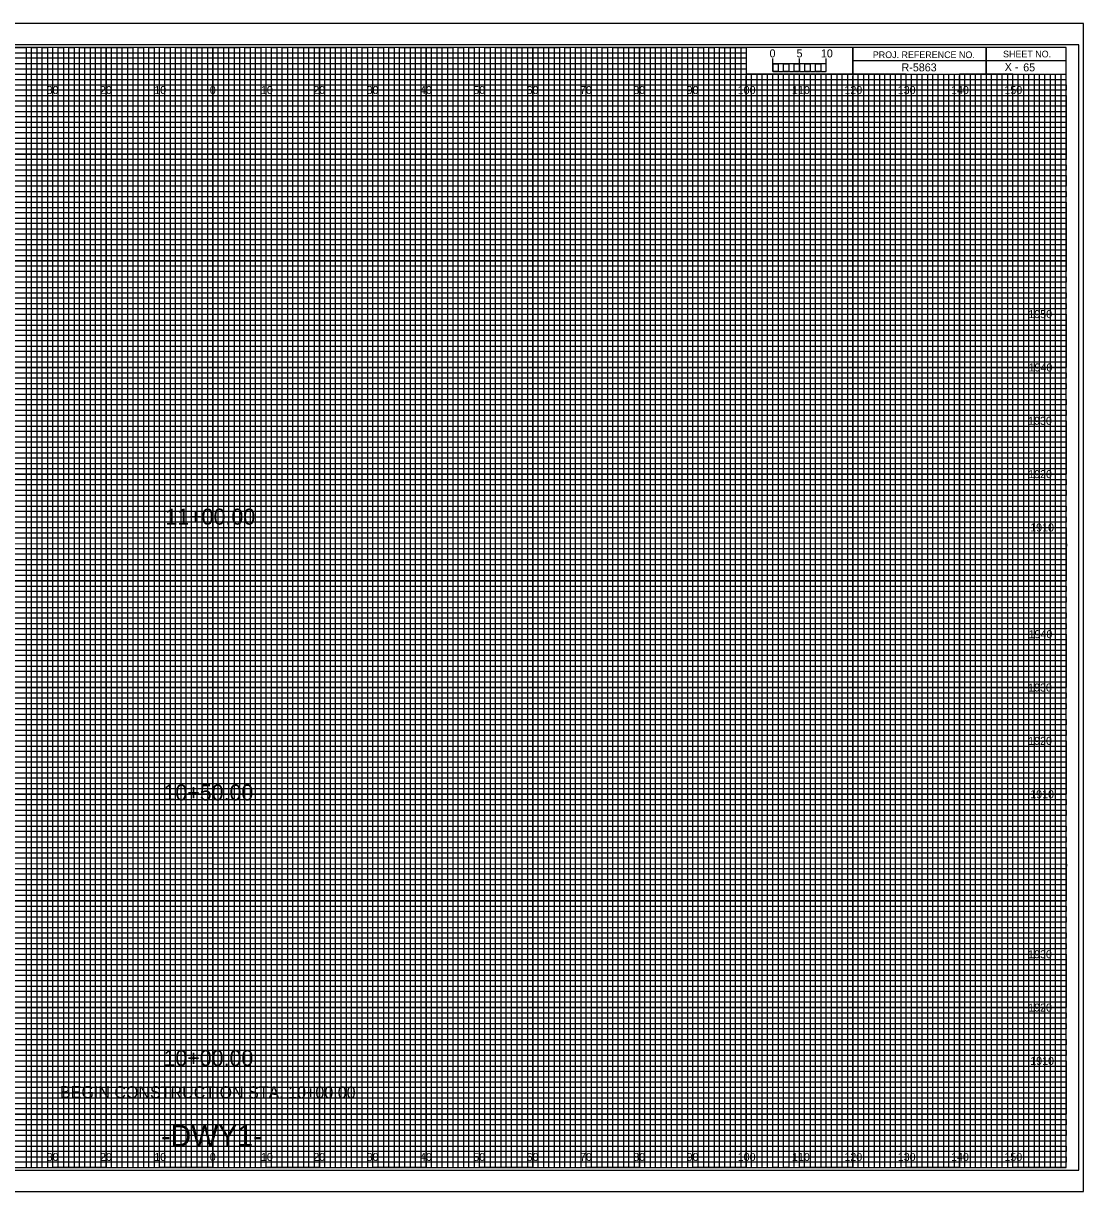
# Model space of a CAD drawing. Extents: x -13 to 323, y -4 to 214.
# Drawn here: x 124.5 to 323.3, y -4.5 to 214.5 of the extents above; entities that cross this region are included whole.
import ezdxf

# ---------------------------------------------------------------- set-up
doc = ezdxf.new("R2010")
doc.units = 0
for name, color, linetype in [('Prop XS Alignment Label', 7, 'Continuous'), ('Prop XS Bar Scale Labels', 7, 'Continuous'), ('Prop XS Elevation Labels', 7, 'Continuous'), ('Prop XS Offset Labels', 7, 'Continuous'), ('Prop XS Project Number', 7, 'Continuous'), ('Prop XS SE Text', 7, 'Continuous'), ('Prop XS Sheet Number', 7, 'Continuous'), ('Prop XS Station Labels', 7, 'Continuous'), ('Sheet Cross Section CELL', 7, 'Continuous'), ('Sheet Cross Section Grid Major CELL', 7, 'Continuous'), ('Sheet Cross Section Grid Middle CELL', 7, 'Continuous'), ('Sheet Cross Section Grid Minor 1 CELL', 7, 'Continuous'), ('Sheet Cross Section Grid Minor 2 CELL', 7, 'Continuous'), ('Sheet Cross Section Scale CELL', 7, 'Continuous'), ('Sheet Cutting Line CELL', 7, 'Continuous'), ('Sheet DOT Grid CELL', 7, 'Continuous'), ('Sheet Plot Border Inside CELL', 7, 'Continuous'), ('Sheet Plot Border Outside CELL', 7, 'Continuous')]:
    doc.layers.add(name, color=color, linetype=linetype)

msp = doc.modelspace()

# ---------------------------------------------------------------- linework, layer by layer
at = {"layer": 'Sheet Cross Section CELL'}
for p, q in [((305, 210), (305, 205)), ((305, 205), (305, 210)), ((280, 207.5), (280, 205)), ((320, 207.49), (280, 207.49)), ((280, 205), (320, 205))]:
    msp.add_line(p, q, dxfattribs=at)
for points in [[(320, 210), (0, 210), (0, 0), (320, 0)], [(280, 210), (260, 210), (260, 205.03), (280, 205.03)], [(320, 210), (280, 210), (280, 205), (320, 205)]]:
    msp.add_lwpolyline(points, close=True, dxfattribs=at)
at = {"layer": 'Sheet Cross Section Grid Major CELL'}
for p, q in [((130, 210), (120, 210)), ((130, 0), (130, 210)), ((150, 210), (140, 210)), ((140, 210), (140, 0)), ((150, 0), (150, 210)), ((170, 210), (160, 210)), ((160, 210), (160, 0)), ((170, 0), (170, 210)), ((190, 210), (180, 210)), ((180, 210), (180, 0)), ((190, 0), (190, 210)), ((210, 210), (200, 210)), ((200, 210), (200, 0)), ((210, 0), (210, 210)), ((230, 210), (220, 210)), ((220, 210), (220, 0)), ((230, 0), (230, 210)), ((250, 210), (240, 210)), ((240, 210), (240, 0)), ((250, 0), (250, 210)), ((260, 210), (260, 0)), ((270, 0), (270, 205)), ((290, 205), (280, 205)), ((280, 205), (280, 0)), ((290, 0), (290, 205)), ((310, 205), (300, 205)), ((300, 205), (300, 0)), ((310, 0), (310, 205)), ((140, 0), (130, 0)), ((160, 0), (150, 0)), ((180, 0), (170, 0)), ((200, 0), (190, 0)), ((220, 0), (210, 0)), ((240, 0), (230, 0)), ((260, 0), (250, 0)), ((280, 0), (270, 0)), ((300, 0), (290, 0)), ((320, 0), (310, 0)), ((320, 0), (320, 0))]:
    msp.add_line(p, q, dxfattribs=at)
for points in [[(0, 200), (320, 200), (320, 190), (0, 190)], [(0, 180), (320, 180), (320, 170), (0, 170)], [(0, 160), (320, 160), (320, 150), (0, 150)], [(0, 140), (320, 140), (320, 130), (0, 130)], [(0, 120), (320, 120), (320, 110), (0, 110)], [(0, 100), (320, 100), (320, 90), (0, 90)], [(0, 80), (320, 80), (320, 70), (0, 70)], [(0, 60), (320, 60), (320, 50), (0, 50)], [(0, 40), (320, 40), (320, 30), (0, 30)], [(0, 20), (320, 20), (320, 10), (0, 10)]]:
    msp.add_lwpolyline(points, dxfattribs=at)
at = {"layer": 'Sheet Cross Section Grid Middle CELL'}
for points in [[(115, 210), (125, 210), (125, 0), (135, 0), (135, 210), (145, 210), (145, 0), (155, 0), (155, 210), (165, 210), (165, 0), (175, 0), (175, 210), (185, 210), (185, 0), (195, 0), (195, 210), (205, 210), (205, 0), (215, 0), (215, 210), (225, 210), (225, 0), (235, 0), (235, 210), (245, 210), (245, 0), (255, 0), (255, 210), (259.93, 210), (260, 210), (260, 205), (264.99, 205), (264.99, 0), (275, 0), (275, 205), (285, 205), (285, 0), (295, 0), (295, 205), (305, 205), (305, 0), (315, 0), (315, 205)], [(0, 205), (275, 205)], [(0, 185), (320, 185), (320, 195), (0, 195)], [(0, 165), (320, 165), (320, 175), (0, 175)], [(0, 145), (320, 145), (320, 155), (0, 155)], [(0, 125), (320, 125), (320, 135), (0, 135)], [(0, 105), (320, 105), (320, 115), (0, 115)], [(0, 85), (320, 85), (320, 95), (0, 95)], [(0, 65), (320, 65), (320, 75), (0, 75)], [(0, 45), (320, 45), (320, 55), (0, 55)], [(0, 25), (320, 25), (320, 35), (0, 35)], [(0, 5), (320, 5), (320, 15), (0, 15)]]:
    msp.add_lwpolyline(points, dxfattribs=at)
at = {"layer": 'Sheet Cross Section Grid Minor 1 CELL'}
for p, q in [((0, 209), (260, 209)), ((260, 209), (260, 207.98)), ((260, 207.98), (0, 207.98)), ((0, 207), (260, 207)), ((260, 205.89), (0, 205.89)), ((260, 207), (260, 205.89)), ((0, 204), (320, 204))]:
    msp.add_line(p, q, dxfattribs=at)
for points in [[(0, 203), (270, 203), (320, 203), (320, 202), (0, 202)], [(0, 201), (320, 201), (320, 199), (0, 199)], [(0, 198), (320, 198), (320, 197), (0, 196.98)], [(0, 196), (320, 196), (320, 194), (0, 194)], [(0, 193), (320, 193), (320, 192), (0, 192)], [(0, 191), (320, 191), (320, 189), (0, 189)], [(0, 188), (320, 188), (320, 187), (0, 187)], [(0, 186), (320, 186), (320, 184), (0, 184)], [(0, 183), (320, 183), (320, 182), (0, 182)], [(0, 181), (320, 181), (320, 179), (0, 179)], [(0, 178), (320, 178), (320, 177), (0, 177)], [(0, 176), (320, 176), (320, 173.95), (320, 173), (320, 172), (0, 172)], [(0, 174), (320, 174), (320, 173), (0, 173)], [(0, 171), (320, 171), (320, 169), (0, 169.03)], [(0, 169.03), (320, 169), (320, 168), (0, 168)], [(0, 167), (320, 167), (320, 166), (0, 166)], [(0, 164), (320, 164), (320, 163), (0, 163)], [(0, 162), (320, 162), (320, 161), (0, 161)], [(-0.07, 158.89), (320, 158.89), (320, 157.88), (-0.07, 157.88)], [(0, 157), (320, 157), (320, 156), (0, 156)], [(0, 154), (320, 154), (320, 153), (0, 153)], [(0, 152), (320, 152), (320, 151), (0, 151)], [(0, 149), (320, 149), (320, 148), (0, 148)], [(0, 147), (320, 147), (320, 146), (0, 146)], [(0, 144), (320, 144), (320, 143), (0, 143)], [(0, 142), (320, 142), (320, 141), (0, 141)], [(0, 139), (320, 139), (319.99, 137.98), (0, 138)], [(0, 137), (320, 137), (320, 136), (0, 136)], [(0, 134), (320, 134), (320, 133), (0, 133)], [(0, 132), (320, 132), (320, 131), (0, 131)], [(0, 129), (320, 129), (320, 128), (0, 128)], [(0, 127), (320, 127), (320, 126), (0, 126)], [(0, 124), (320, 124), (320, 123), (0, 123)], [(0, 122), (320, 122), (320, 121), (0, 121)], [(0, 119), (320, 119), (320, 118), (0, 118)], [(0, 116.99), (320.07, 116.91), (320, 116), (0, 116)], [(0, 114), (320, 114), (320, 113), (0, 113)], [(0, 112), (320, 112), (320, 111), (0, 111)], [(0, 109), (320, 109), (320, 108), (0, 108)], [(0, 107), (320, 107), (320, 106), (0, 106)], [(0, 104), (320, 104), (320, 103), (0, 103)], [(0, 102), (320, 102), (320, 101), (0, 101)], [(0, 99), (320, 99), (320, 98), (0, 98)], [(0, 97), (320, 97), (320, 96), (0, 96)], [(0, 94), (320, 94), (320, 93), (0, 93)], [(0, 92), (320, 92), (320, 91), (0, 91)], [(0, 89), (320, 89), (320, 88), (0, 88)], [(0, 87), (320, 87), (320, 86), (0, 86)], [(0, 84), (320, 84), (320, 83), (0, 83)], [(0, 82), (320, 82), (320, 81), (0, 81)], [(0, 79), (320, 79), (319.99, 77.98), (0, 78)], [(0, 77), (320, 77), (320, 76), (0, 76)], [(0, 74), (320, 74), (320, 73), (0, 73)], [(0, 72), (320, 72), (320, 71), (0, 71)], [(0, 69), (320, 69), (320, 68), (0, 68)], [(0, 67), (320, 67), (320, 66), (0, 66)], [(0, 64), (320, 64), (320, 63), (0, 63)], [(0, 62), (320, 62), (320, 61), (0, 61)], [(0, 59), (320, 59), (320, 58), (0, 58)], [(0, 56.99), (320.07, 56.91), (320, 56), (0, 56)], [(0, 54), (320, 54), (320, 53), (0, 53)], [(0, 52), (320, 52), (320, 51), (0, 51)], [(0, 49), (320, 49), (320, 48), (0, 48)], [(0, 47), (320, 47), (320, 46), (0, 46)], [(0, 44), (320, 44), (320, 43), (0, 43)], [(0, 42), (320, 42), (320, 41), (0, 41)], [(0, 39), (320, 39), (320, 38), (0, 38)], [(0, 37), (320, 37), (320, 36), (0, 36)], [(0, 34), (320, 34), (320, 33), (0, 33)], [(0, 32), (320, 32), (320, 31), (0, 31)], [(0, 29), (320, 29), (320, 28), (0, 28)], [(0, 27), (320, 27), (320, 26), (0, 26)], [(0, 24), (320, 24), (320, 23), (0, 23)], [(0, 22), (320, 22), (320, 21), (0, 21)], [(0, 19), (320, 19), (320, 18), (0, 18)], [(0, 17), (320, 17), (320, 16), (0, 16)], [(0, 14), (320, 14), (320, 13), (0, 13)], [(0, 12), (320, 12), (320, 11), (0, 11)], [(0, 9), (320, 9), (320, 8), (0, 8)], [(0, 7), (320, 7), (320, 6), (0, 6)], [(0, 4), (320, 4), (320, 3), (0, 3)], [(0, 2), (320, 2), (320, 1), (0, 1)]]:
    msp.add_lwpolyline(points, dxfattribs=at)
at = {"layer": 'Sheet Cross Section Grid Minor 2 CELL'}
for p, q in [((267, 205), (266.01, 205)), ((266.01, 205), (266.01, 0)), ((267, 0), (267, 205)), ((269, 205), (268, 205)), ((268, 205), (268, 0)), ((269, 0), (269, 205)), ((266.01, 0), (265, 0)), ((268, 0), (267, 0))]:
    msp.add_line(p, q, dxfattribs=at)
for points in [[(125, 0), (126, 0), (126, 210), (127, 210), (127, 0)], [(127, 0), (128, 0), (128, 210), (129, 210), (129, 0)], [(130, 0), (131, 0), (131, 210), (132, 210), (132, 0)], [(132, 0), (133, 0), (133, 210), (134, 210), (134, 0)], [(135, 0), (136, 0), (136, 210), (137, 210), (137, 0)], [(137, 0), (138, 0), (138, 210), (139, 210), (139, 0)], [(140, 0), (141, 0), (141, 210), (142, 210), (142, 0)], [(142, 0), (143, 0), (143, 210), (144, 210), (144, 0)], [(145, 0), (146, 0), (146, 210), (147, 210), (147, 0)], [(147, 0), (148, 0), (148, 210), (149, 210), (149, 0)], [(150, 0), (151, 0), (151, 210), (152, 210), (152, 0)], [(152, 0), (153, 0), (153, 210), (154, 210), (154, 0)], [(155, 0), (156, 0), (156, 210), (157, 210), (157, 0)], [(157, 0), (158, 0), (158, 210), (159, 210), (159, 0)], [(160, 0), (161, 0), (161, 210), (162, 210), (162, 0)], [(162, 0), (163, 0), (163, 210), (164, 210), (164, 0)], [(165, 0), (166, 0), (166, 210), (167, 210), (167, 0)], [(167, 0), (168, 0), (168, 210), (169, 210), (169, 0)], [(170, 0), (171, 0), (171, 210), (172, 210), (172, 0)], [(172, 0), (173, 0), (173, 210), (174, 210), (174, 0)], [(175, 0), (176, 0), (176, 210), (177, 210), (177, 0)], [(177, 0), (178, 0), (178, 210), (179, 210), (179, 0)], [(180, 0), (181, 0), (181, 210), (182, 210), (182, 0)], [(182, 0), (183, 0), (183, 210), (184, 210), (184, 0)], [(185, 0), (186, 0), (186, 210), (187, 210), (187, 0)], [(187, 0), (188, 0), (188, 210), (189, 210), (189, 0)], [(190, 0), (191, 0), (191, 210), (192, 210), (192, 0)], [(192, 0), (193, 0), (193, 210), (194, 210), (194, 0)], [(195, 0), (196, 0), (196, 210), (197, 210), (197, 0)], [(197, 0), (198, 0), (198, 210), (199, 210), (199, 0)], [(200, 0), (201, 0), (201, 210), (202, 210), (202, 0)], [(202, 0), (203, 0), (203, 210), (204, 210), (204, 0)], [(205, 0), (206, 0), (206, 210), (207, 210), (207, 0)], [(207, 0), (208, 0), (208, 210), (209, 210), (209, 0)], [(210, 0), (211, 0), (211, 210), (212, 210), (212, 0)], [(212, 0), (213, 0), (213, 210), (214, 210), (214, 0)], [(215, 0), (216, 0), (216, 210), (217, 210), (217, 0)], [(217, 0), (218, 0), (218, 210), (219, 210), (219, 0)], [(220, 0), (221, 0), (221, 210), (222, 210), (222, 0)], [(222, 0), (223, 0), (223, 210), (224, 210), (224, 0)], [(225, 0), (226, 0), (226, 210), (227, 210), (227, 0)], [(227, 0), (228, 0), (228, 210), (229, 210), (229, 0)], [(230, 0), (231, 0), (231, 210), (232, 210), (232, 0)], [(232, 0), (233, 0), (233, 210), (234, 210), (234, 0)], [(235, 0), (236, 0), (236, 210), (237, 210), (237, 0)], [(237, 0), (238, 0), (238, 210), (239, 210), (239, 0)], [(240, 0), (241, 0), (241, 210), (242, 210), (242, 0)], [(242, 0), (243, 0), (243, 210), (244, 210), (244, 0)], [(245, 0), (246, 0), (246, 210), (247, 210), (247, 0)], [(247, 0), (248, 0), (248, 210), (249, 210), (249, 0)], [(250, 0), (251, 0), (251, 210), (252, 210), (252, 0)], [(252, 0), (253, 0), (253, 210), (254, 210), (254, 0)], [(255, 0), (256, 0), (256, 210), (257, 210), (257, 0)], [(257, 0), (258, 0), (258, 210), (259, 210), (259, 0)], [(260, 0), (261, 0), (261, 205), (262.02, 205), (262.02, 0)], [(262, 0), (263, 0), (263, 205), (263.99, 205), (263.99, 0)], [(270, 0), (270.98, 0), (270.98, 205), (272, 205), (272, 0)], [(272, 0), (273, 0), (273, 205), (274.05, 205), (274.05, 0)], [(275, 0), (276, 0), (276, 205), (277, 205), (277, 0)], [(277, 0), (278, 0), (278, 205), (279, 205), (279, 0)], [(280, 0), (281, 0), (281, 205), (282, 205), (282, 0)], [(282, 0), (283, 0), (283, 205), (284, 205), (284, 0)], [(285, 0), (286, 0), (286, 205), (287, 205), (287, 0)], [(287, 0), (288, 0), (288, 205), (289, 205), (289, 0)], [(290, 0), (291, 0), (291, 205), (292, 205), (292, 0)], [(292, 0), (293, 0), (293, 205), (294, 205), (294, 0)], [(295, 0), (296, 0), (296, 205), (297, 205), (297, 0)], [(297, 0), (298, 0), (298, 205), (299, 205), (299, 0)], [(300, 0), (301, 0), (301, 205), (302, 205), (302, 0)], [(302, 0), (303, 0), (303, 205), (304, 205), (304, 0)], [(305, 0), (306, 0), (306, 205), (307, 205), (307, 0)], [(307, 0), (308, 0), (308, 205), (309, 205), (309, 0)], [(310, 0), (311, 0), (311, 205), (312, 205), (312, 0)], [(312, 0), (313, 0), (313, 205), (314, 205), (314, 0)], [(315, 0), (316, 0), (316, 205), (317, 205), (317, 0)], [(317, 0), (318, 0), (318, 205), (319, 205), (319, 0)]]:
    msp.add_lwpolyline(points, dxfattribs=at)
at = {"layer": 'Sheet Cross Section Scale CELL'}
for p, q in [((265, 205.49), (265, 207.9)), ((265, 206.9), (265, 207.9)), ((270, 205.49), (270, 207.9)), ((275, 205.49), (275, 207.9)), ((275, 206.9), (275, 207.9))]:
    msp.add_line(p, q, dxfattribs=at)
for points in [[(275, 206.9), (265, 206.9), (265, 205.49), (275, 205.49)], [(265, 206.9), (266, 206.9), (266, 205.49), (265, 205.49)], [(267, 206.9), (268, 206.9), (268, 205.49), (267, 205.49)], [(269, 206.9), (270, 206.9), (270, 205.49), (269, 205.49)], [(271, 206.9), (272, 206.9), (272, 205.49), (271, 205.49)], [(273, 206.9), (274, 206.9), (274, 205.49), (273, 205.49)]]:
    msp.add_lwpolyline(points, close=True, dxfattribs=at)
at = {"layer": 'Sheet Cutting Line CELL'}
for p, q in [((323.3, 214.5), (-13.4, 214.5)), ((-13.4, -4.5), (323.3, -4.5))]:
    msp.add_line(p, q, dxfattribs=at)
at = {"layer": 'Sheet DOT Grid CELL'}
for p, q in [((130, 0), (130, 210)), ((140, 0), (140, 210)), ((150, 0), (150, 210)), ((160, 0), (160, 210)), ((170, 0), (170, 210)), ((180, 0), (180, 210)), ((190, 0), (190, 210)), ((200, 0), (200, 210)), ((210, 0), (210, 210)), ((220, 0), (220, 210)), ((230, 0), (230, 210)), ((240, 0), (240, 210)), ((250, 0), (250, 210)), ((260, 0), (260, 204.69)), ((270, 0), (270, 204.69)), ((280, 0), (280, 204.69)), ((290, 0), (290, 204.69)), ((300, 0), (300, 204.69)), ((310, 0), (310, 204.69)), ((0, 200), (320, 200)), ((0, 190), (320, 190)), ((0, 180), (320, 180)), ((0, 170), (320, 170)), ((0, 160), (320, 160)), ((0, 150), (320, 150)), ((0, 140), (320, 140)), ((0, 130), (320, 130)), ((0, 120), (320, 120)), ((0, 110), (320, 110)), ((0, 100), (320, 100)), ((0, 90), (320, 90)), ((0, 80), (320, 80)), ((0, 70), (320, 70)), ((0, 60), (320, 60)), ((0, 50), (320, 50)), ((0, 40), (320, 40)), ((0, 30), (320, 30)), ((0, 20), (320, 20)), ((0, 10), (320, 10))]:
    msp.add_line(p, q, dxfattribs=at)
at = {"layer": 'Sheet Plot Border Inside CELL'}
msp.add_lwpolyline([(-10.8, -0.5), (322.4, -0.5), (322.4, 210.5), (-10.8, 210.5)], close=True, dxfattribs=at)
at = {"layer": 'Sheet Plot Border Outside CELL'}
msp.add_lwpolyline([(-13.4, -4.5), (323.3, -4.5), (323.3, 214.5), (-13.4, 214.5)], close=True, dxfattribs=at)

# ---------------------------------------------------------------- texts
at = {"layer": 'Prop XS Alignment Label'}
msp.add_text('-DWY1-', height=4, dxfattribs=at).set_placement((150.33, 4))
at = {"layer": 'Prop XS Bar Scale Labels'}
for s, p in [('5', (269.47, 208.12)), ('10', (274.04, 208.12))]:
    msp.add_text(s, height=1.5, dxfattribs=at).set_placement(p)
at = {"layer": 'Prop XS Elevation Labels'}
for s, p in [('1950', (312.92, 159.25)), ('1940', (312.97, 149.25)), ('1930', (312.89, 139.25)), ('1920', (312.9, 129.25)), ('1910', (313.28, 119.25)), ('1940', (312.97, 99.25)), ('1930', (312.89, 89.25)), ('1920', (312.9, 79.25)), ('1910', (313.28, 69.25)), ('1930', (312.89, 39.25)), ('1920', (312.9, 29.25)), ('1910', (313.28, 19.25))]:
    msp.add_text(s, height=1.5, dxfattribs=at).set_placement(p)
at = {"layer": 'Prop XS Offset Labels'}
for s, p in [('30', (128.86, 201.25)), ('20', (138.86, 201.25)), ('10', (149.04, 201.25)), ('0', (159.45, 201.25)), ('0', (159.45, 201.25)), ('10', (169.04, 201.25)), ('20', (178.86, 201.25)), ('30', (188.86, 201.25)), ('40', (198.86, 201.25)), ('50', (208.86, 201.25)), ('60', (218.86, 201.25)), ('70', (228.86, 201.25)), ('80', (238.86, 201.25)), ('90', (248.86, 201.25)), ('100', (258.44, 201.25)), ('110', (268.62, 201.25)), ('120', (278.44, 201.25)), ('130', (288.44, 201.25)), ('140', (298.44, 201.25)), ('150', (308.44, 201.25)), ('30', (128.86, 1.25)), ('20', (138.86, 1.25)), ('10', (149.04, 1.25)), ('0', (159.45, 1.25)), ('0', (159.45, 1.25)), ('10', (169.04, 1.25)), ('20', (178.86, 1.25)), ('30', (188.86, 1.25)), ('40', (198.86, 1.25)), ('50', (208.86, 1.25)), ('60', (218.86, 1.25)), ('70', (228.86, 1.25)), ('80', (238.86, 1.25)), ('90', (248.86, 1.25)), ('100', (258.44, 1.25)), ('110', (268.62, 1.25)), ('120', (278.44, 1.25)), ('130', (288.44, 1.25)), ('140', (298.44, 1.25)), ('150', (308.44, 1.25))]:
    msp.add_text(s, height=1.5, dxfattribs=at).set_placement(p)
at = {"layer": 'Prop XS Project Number'}
msp.add_text('R-5863', height=1.5, dxfattribs=at).set_placement((289.16, 205.5))
at = {"layer": 'Prop XS SE Text'}
msp.add_text('BEGIN CONSTRUCTION STA. 10+00.00', height=2.25, rotation=359.9258, dxfattribs=at).set_placement((131.36, 13.04))
at = {"layer": 'Prop XS Sheet Number'}
msp.add_text('65', height=1.5, dxfattribs=at).set_placement((311.97, 205.5))
at = {"layer": 'Prop XS Station Labels'}
for s, p in [('11+00.00', (151.13, 120.53)), ('10+50.00', (150.77, 68.83)), ('10+00.00', (150.77, 19.05))]:
    msp.add_text(s, height=3, dxfattribs=at).set_placement(p)
at = {"layer": 'Sheet Cross Section CELL'}
for s, height, p in [('PROJ. REFERENCE NO.', 1.25, (283.77, 207.99)), ('SHEET NO.', 1.25, (308.19, 208.12)), ('X -    ', 1.5, (308.5, 205.58))]:
    msp.add_text(s, height=height, dxfattribs=at).set_placement(p)
at = {"layer": 'Sheet Cross Section Scale CELL'}
msp.add_text('0', height=1.5, dxfattribs=at).set_placement((264.41, 208.12))

doc.saveas('drawing.dxf')
